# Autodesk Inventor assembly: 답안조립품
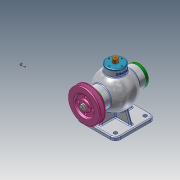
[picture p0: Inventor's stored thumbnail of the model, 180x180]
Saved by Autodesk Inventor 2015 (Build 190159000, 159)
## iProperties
Created: 2025-08
Part Number: 답안조립품
Document SubType Name: Assembly
Designer: USER
Author: USER
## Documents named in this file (15)
- C:\Users\USER\Downloads\750808V1010\답안조립품.iam
- C:\Users\USER\Downloads\750808V1010\본체.ipt
- C:\Users\USER\Downloads\750808V1010\가져온 구성요소\V-벨트풀리\V-벨트풀리.ipt
- C:\Users\USER\Downloads\750808V1010\가져온 구성요소\너트 M8\너트 M8.ipt
- C:\Users\USER\Downloads\750808V1010\가져온 구성요소\뒤커버\뒤커버.ipt
- C:\Users\USER\Downloads\750808V1010\가져온 구성요소\베어링- 6202\베어링- 6202.ipt
- C:\Users\USER\Downloads\750808V1010\가져온 구성요소\볼트 M4 x 12\볼트 M4 x 12.ipt
- C:\Users\USER\Downloads\750808V1010\가져온 구성요소\볼트 M4 x 16\볼트 M4 x 16.ipt
- C:\Users\USER\Downloads\750808V1010\가져온 구성요소\상부커버\상부커버.ipt
- C:\Users\USER\Downloads\750808V1010\가져온 구성요소\슬라이드\슬라이드.ipt
- C:\Users\USER\Downloads\750808V1010\가져온 구성요소\앞커버\앞커버.ipt
- C:\Users\USER\Downloads\750808V1010\가져온 구성요소\오일실 15 30 7\오일실 15 30 7.ipt
- C:\Users\USER\Downloads\750808V1010\가져온 구성요소\칼라\칼라.ipt
- C:\Users\USER\Downloads\750808V1010\가져온 구성요소\키 4 x 4 x 12\키 4 x 4 x 12.ipt
- C:\Users\USER\Downloads\750808V1010\가져온 구성요소\편심축\편심축.ipt
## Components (1 placed, 1 different names)
1. V-벨트풀리:1 — 플러쉬:4
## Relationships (1: Flush 1)
- 플러쉬:4 [Flush]: V-벨트풀리:1
